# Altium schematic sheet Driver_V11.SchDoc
size 302 x 215 mm; PageSetup: Record=PageOptions|CenterHorizontal=True|CenterVertical=True|PrintScale=1.55|XCorrection=1.00|YCorrection=1.00|PrintKind=1|BorderSize=5000000|LeftOffset=0|BottomOffset=0|Orientation=1|PaperLength=1000|PaperWidth=1000|Scale=100|PaperSource=7|PrintQuality=-4|MediaType=1|DitherType=10|PaperKind=A4 (210 x 297 mm)|PrintScaleMode=1
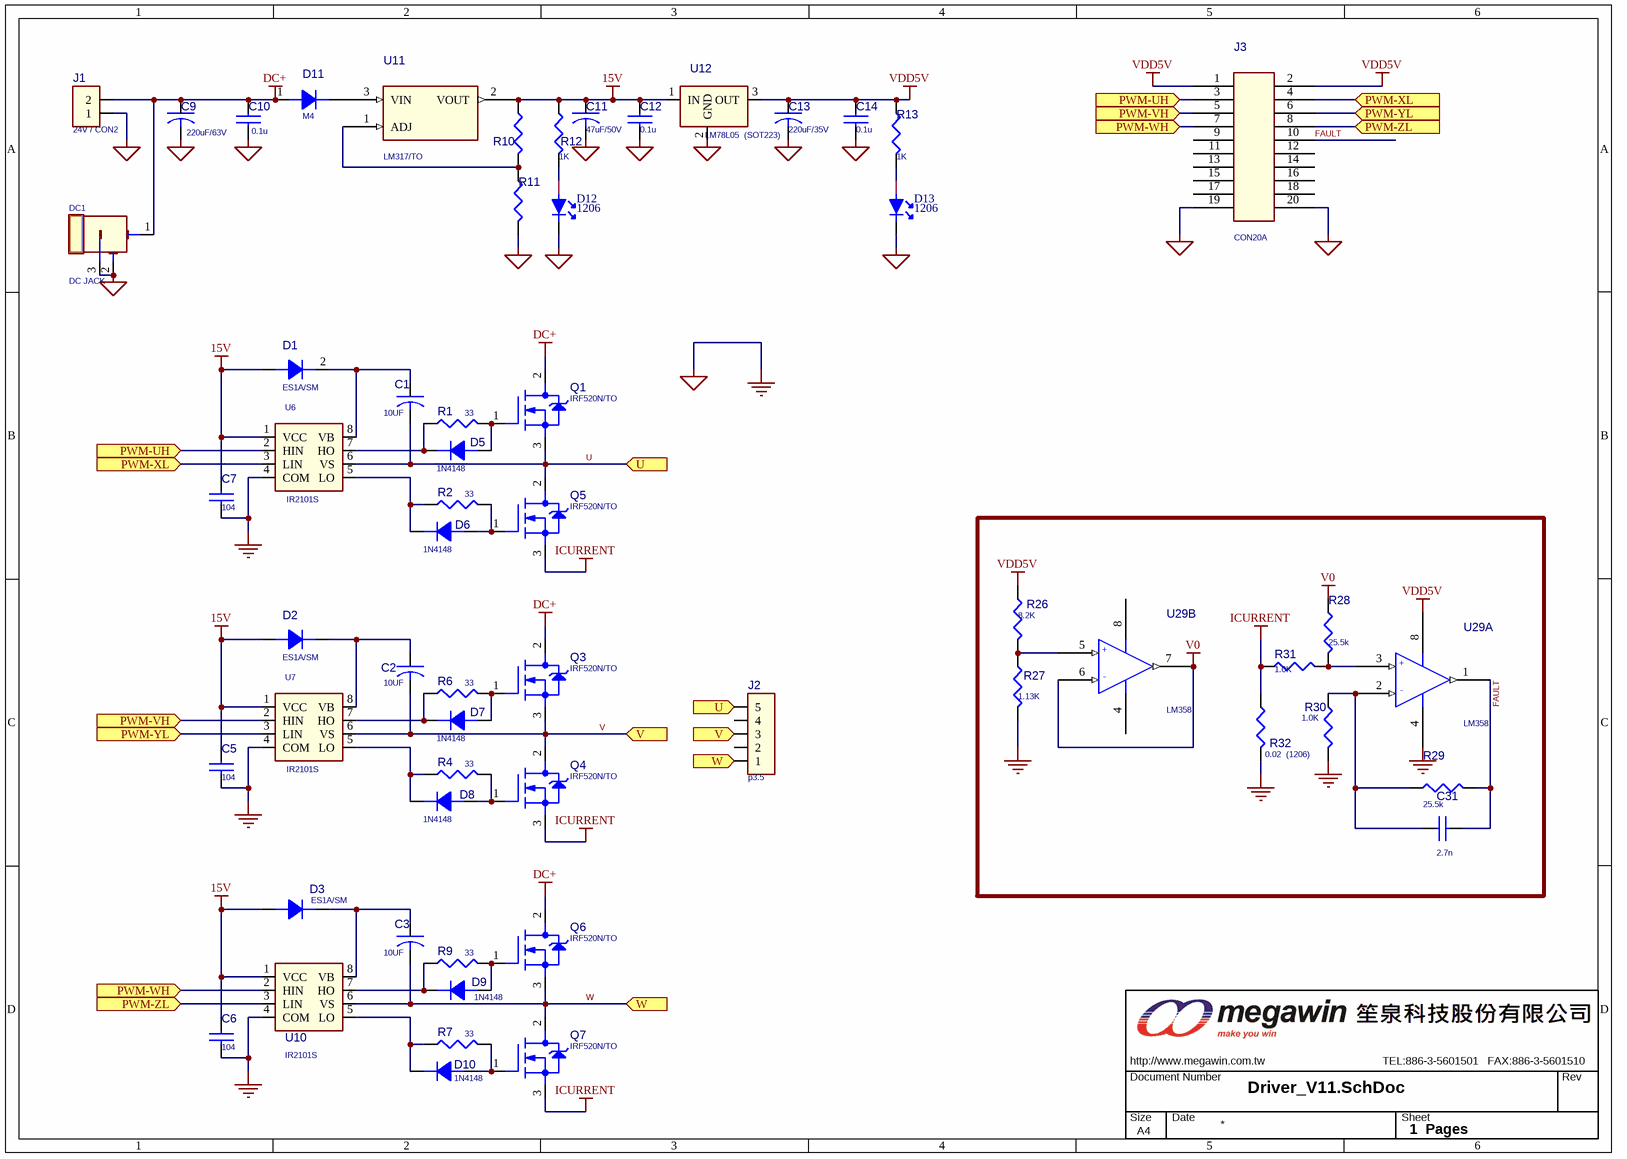
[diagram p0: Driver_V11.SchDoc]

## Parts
C1  10UF  [1206C]
C2  10UF  [1206C]
C3  10UF  [1206C]
C5  104  [0805C]
C6  104  [0805C]
C7  104  [0805C]
C9  220uF/63V  [CEC102P050]
C10  0.1u  [0805C]
C11  47uF/50V  [CEC063P025]
C12  0.1u  [0805C]
C13  220uF/35V  [CEC082P035]
C14  0.1u  [0805C]
C31  2.7n  [0805C]
D1  ES1A/SM  [DIODE_SMA]
D2  ES1A/SM  [DIODE_SMA]
D3  ES1A/SM  [DIODE_SMA]
D5  1N4148  [D4148_SMD]
D6  1N4148  [D4148_SMD]
D7  1N4148  [D4148_SMD]
D8  1N4148  [D4148_SMD]
D9  1N4148  [D4148_SMD]
D10  1N4148  [D4148_SMD]
D11  M4  [DIODE_SMA]
D12  1206  [1206D]
D13  1206  [1206D]
DC1  DC JACK  [JACK_DC_0]
J1  24V / CON2  [PW2P3.5_90]
J2  p3.5  [PW5P3.5_90]
J3  CON20A  [PS10X2P254_90]
MW1  OrgAddr3: TEL:886-3-5601501   FAX:886-3-5601510  Page Size: A4  [MEGAWIN_3.4]  (hidden comment: MW-A4)  (no BOM)
Q1  IRF520N/TO  [TO220HL18X15.3]
Q3  IRF520N/TO  [TO220HL18X15.3]
Q4  IRF520N/TO  [TO220HL18X15.3]
Q5  IRF520N/TO  [TO220HL18X15.3]
Q6  IRF520N/TO  [TO220HL18X15.3]
Q7  IRF520N/TO  [TO220HL18X15.3]
R1  33  [0805R]
R2  33  [0805R]
R4  33  [0805R]
R6  33  [0805R]
R7  33  [0805R]
R9  33  [0805R]
R10  RESISTOR  [0805R]  (value not drawn)
R11  RESISTOR  [0805R]  (value not drawn)
R12  1K  [0805R]
R13  1K  [0805R]
R26  8.2K  [0805R]
R27  1.13K  [0805R]
R28  25.5k  [0805R]
R29  25.5k  [0805R]
R30  1.0K  [0805R]
R31  1.0K  [0805R]
R32  0.02  (1206)  [1206R]
U6  IR2101S  [SO8_150P127]
U7  IR2101S  [SO8_150P127]
U10  IR2101S  [SO8_150P127]
U11  LM317/TO  [TO220HL18X15.3]
U12  LM78L05  (SOT223)  [sot223]
U29  LM358  [SO8_150P127]  (parts A,B of 2)

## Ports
PWM-UH (in), PWM-VH (in), PWM-WH (in), PWM-XL (in), PWM-YL (in), PWM-ZL (in), U (in), V (in), W (in)

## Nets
15V: C5.1 C6.1 C7.1 C11.1 C12.1 D1.1(ANODE) D2.1(ANODE) D3.1(ANODE) R10.1 R12.1 U6.1(VCC) U7.1(VCC) U10.1(VCC) U11.2(VOUT) U12.1(IN)
DC+: C9.1 C10.1 D11.1(A) DC1.1(DC+) J1.2 Q1.2(D) Q3.2(D) Q6.2(D)
GND: C5.2 C6.2 C7.2 C9.2 C10.2 C11.2 C12.2 C13.2 C14.2 D12.2 D13.2 DC1.2(NA) DC1.3(DC-) J1.1 J3.19 J3.20 R11.2 R27.2 R30.2 R32.2 U6.4(COM) U7.4(COM) U10.4(COM) U12.2(GND) U29.4(GND)  [also labelled GND_FIELD SIGNAL]
ICURRENT: Q4.3(S) Q5.3(S) Q7.3(S) R31.1 R32.1
V0: R28.1 U29.6(-IN) U29.7(OUT)
VDD5V: C13.1 C14.1 J3.1 J3.2 R13.1 R26.1 U12.3(OUT) U29.8(VCC)
FAULT: C31.2 J3.10 R29.2 U29.1(OUT)
PWM-UH: J3.3 U6.2(HIN) ; port PWM-UH
PWM-VH: J3.5 U7.2(HIN) ; port PWM-VH
PWM-WH: J3.7 U10.2(HIN) ; port PWM-WH
PWM-XL: J3.4 U6.3(LIN) ; port PWM-XL
PWM-YL: J3.6 U7.3(LIN) ; port PWM-YL
PWM-ZL: J3.8 U10.3(LIN) ; port PWM-ZL
U: C1.2 J2.5 Q1.3(S) Q5.2(D) U6.6(VS) ; port U
V: C2.2 J2.3 Q3.3(S) Q4.2(D) U7.6(VS) ; port V
W: C3.2 J2.1 Q6.3(S) Q7.2(D) U10.6(VS) ; port W
NetC1_1: C1.1 D1.2(CATHODE) U6.8(VB)
NetC2_1: C2.1 D2.2(CATHODE) U7.8(VB)
NetC3_1: C3.1 D3.2(CATHODE) U10.8(VB)
NetC31_1: C31.1 R29.1 R30.1 U29.2(-IN)
NetD5_1: D5.1(ANODE) Q1.1(G) R1.2
NetD5_2: D5.2(CATHODE) R1.1 U6.7(HO)
NetD6_1: D6.1(ANODE) Q5.1(G) R2.2
NetD6_2: D6.2(CATHODE) R2.1 U6.5(LO)
NetD7_1: D7.1(ANODE) Q3.1(G) R6.2
NetD7_2: D7.2(CATHODE) R6.1 U7.7(HO)
NetD8_1: D8.1(ANODE) Q4.1(G) R4.2
NetD8_2: D8.2(CATHODE) R4.1 U7.5(LO)
NetD9_1: D9.1(ANODE) Q6.1(G) R9.2
NetD9_2: D9.2(CATHODE) R9.1 U10.7(HO)
NetD10_1: D10.1(ANODE) Q7.1(G) R7.2
NetD10_2: D10.2(CATHODE) R7.1 U10.5(LO)
NetD11_2: D11.2(K) U11.3(VIN)
NetD12_1: D12.1 R12.2
NetD13_1: D13.1 R13.2
NetR10_2: R10.2 R11.1 U11.1(ADJ)
NetR26_2: R26.2 R27.1 U29.5(+IN)
NetR28_2: R28.2 R31.2 U29.3(+IN)

Not connected (* = marked no-connect by the designer): J2 2 4; J3 9 11 12 13 14 15 16 17 18

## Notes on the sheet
- 1  Pages

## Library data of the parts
C1-C3 C9 C11 C13 = CAP
C5-C7 C10 C12 C14 C31 = CAP NP
D11 = DIODE
D12 D13 = LED_SC
DC1 = JACK_DC2
J1 = CON2
J2 = CON5
MW1 = MW_A4_1
R1 R2 R4 R6 R7 R9 R12 R13 R26-R32 = RESISTOR
U12 = LM78L05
